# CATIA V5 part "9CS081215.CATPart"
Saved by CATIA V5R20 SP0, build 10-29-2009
Part number: 9CS081215
Revision: ANY
Definition: UNKNOWN
Nomenclature: 9CS081215
Source: Unknown
Bounding box of the stored display mesh (mm): x -5.85 to 5.85, y -7.5 to 7.5, z -6 to 6
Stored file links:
  C:\Users\Utente\Desktop\IO LAVORO\3D X SITO CF\CUMSA\3D files PW\pw081230\pw081230_ejection\9CS081215.CATPart
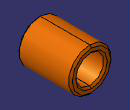
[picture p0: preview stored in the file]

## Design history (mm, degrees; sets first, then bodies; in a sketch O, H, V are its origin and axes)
Body1 "Revolución1" (main body)
  Solid1: solid without history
